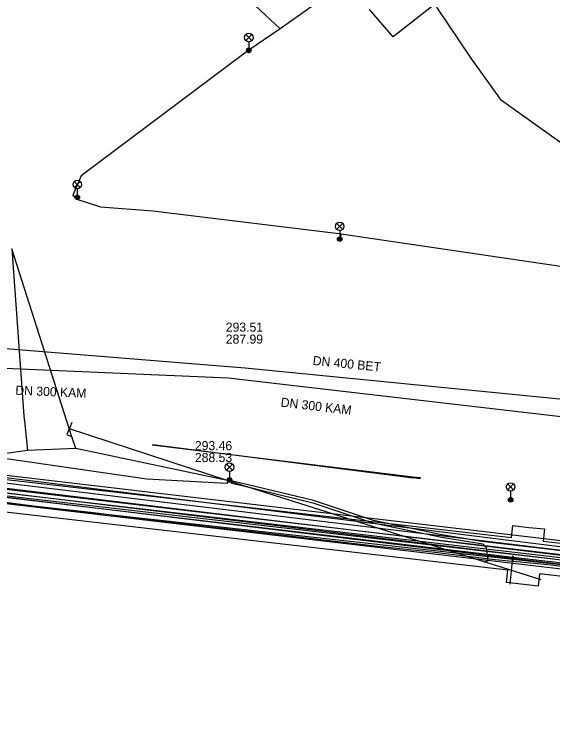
# Model space of a CAD drawing. Extents: x -595540 to -593988, y -1160850 to -1159202.
# Drawn here: x -594463.4 to -594416.1, y -1160027 to -1159965.4 of the extents above; entities that cross this region are included whole.
import ezdxf

# ---------------------------------------------------------------- set-up
doc = ezdxf.new("R2010")
doc.units = 0
for name, color, linetype in [('BKOM-ODVODNENI_trasa sítě', 7, 'Continuous'), ('BVK-DESTOVA_popisy', 7, 'Continuous'), ('BVK-DESTOVA_trasa sítě', 7, 'Continuous'), ('BVK-SPLASKOVA_popisy', 7, 'Continuous'), ('BVK-SPLASKOVA_trasa sítě', 7, 'Continuous'), ('BVK-VODOVOD_trasa sítě', 7, 'Continuous'), ('BVK-VODOVOD_trasa zrušené sítě', 7, 'Continuous'), ('CETIN_kabel podzemní', 7, 'Continuous'), ('DESTOVA_trasa neprovozované sítě', 7, 'Continuous'), ('DPMB_trolejové vedení-nosné lano', 7, 'Continuous'), ('DSP-NN-TEPLARNY_kabel', 7, 'Continuous'), ('EON-VN_kabel', 7, 'Continuous'), ('PODA_kabel optický', 7, 'Continuous'), ('QUANTCOM_kabel v kolektoru_kabelovodu', 7, 'Continuous'), ('TEPLARNY-ELEKTRO_kabel', 7, 'Continuous'), ('TEPLARNY-HORKOVODY_trasa sítě', 7, 'Continuous'), ('TEPLARNY-HORKOVODY_trasa sítě obvodem', 7, 'Continuous'), ('TSB_kabel VO', 7, 'Continuous'), ('TSB_kolektor', 7, 'Continuous'), ('TSB_lampy VO', 7, 'Continuous')]:
    doc.layers.add(name, color=color, linetype=linetype)

msp = doc.modelspace()

# ---------------------------------------------------------------- linework, layer by layer
at = {"layer": 'BKOM-ODVODNENI_trasa sítě'}
for points in [[(-594428.368, -1160006.091), (-594451.23, -1160003.162)], [(-594428.383, -1160006.029), (-594427.719, -1160006.112)]]:
    msp.add_lwpolyline(points, dxfattribs=at)
at = {"layer": 'BVK-DESTOVA_popisy'}
msp.add_line((-594444.809, -1159993.367), (-594444.809, -1159993.367), dxfattribs=at)
at = {"layer": 'BVK-DESTOVA_trasa sítě'}
for p, q in [((-594443.105, -1159996.452), (-594483.447, -1159993.19)), ((-594402.759, -1160000.428), (-594443.105, -1159996.452))]:
    msp.add_line(p, q, dxfattribs=at)
at = {"layer": 'BVK-SPLASKOVA_popisy'}
msp.add_line((-594447.523, -1160002.842), (-594447.523, -1160002.842), dxfattribs=at)
at = {"layer": 'BVK-SPLASKOVA_trasa sítě'}
for p, q in [((-594444.614, -1159997.319), (-594485.93, -1159995.524)), ((-594404.05, -1160002.016), (-594444.614, -1159997.319))]:
    msp.add_line(p, q, dxfattribs=at)
at = {"layer": 'BVK-VODOVOD_trasa sítě'}
for points in [[(-594469.9, -1160007.53), (-594469.248, -1160007.595), (-594468.467, -1160007.674), (-594466.45, -1160007.9), (-594461.46, -1160008.54), (-594456.43, -1160009.12), (-594451.43, -1160009.74), (-594446.44, -1160010.34), (-594441.42, -1160010.9), (-594436.47, -1160011.48), (-594431.46, -1160012.05), (-594426.45, -1160012.6), (-594421.45, -1160013.19), (-594419.668, -1160013.381), (-594419.581, -1160013.39), (-594416.24, -1160013.71), (-594411.23, -1160014.31)], [(-594419.581, -1160013.39), (-594419.55, -1160012.962), (-594419.629, -1160012.953), (-594419.64, -1160013.07), (-594419.86, -1160015.39)]]:
    msp.add_lwpolyline(points, dxfattribs=at)
at = {"layer": 'BVK-VODOVOD_trasa zrušené sítě'}
msp.add_lwpolyline([(-594469.49, -1160007.15), (-594467.97, -1160007.316), (-594419.34, -1160013.06), (-594377.5, -1160017.89), (-594368.46, -1160018.9)], dxfattribs=at)
at = {"layer": 'CETIN_kabel podzemní'}
msp.add_lwpolyline([(-594467.2, -1160005.67), (-594372.02, -1160017.5)], dxfattribs=at)
at = {"layer": 'DESTOVA_trasa neprovozované sítě'}
for p, q in [((-594428.377, -1160006.011), (-594451.265, -1160003.201)), ((-594427.718, -1160006.067), (-594428.377, -1160006.011))]:
    msp.add_line(p, q, dxfattribs=at)
at = {"layer": 'DPMB_trolejové vedení-nosné lano'}
for points in [[(-594458.32, -1160002.47), (-594463.59, -1159985.96)], [(-594463.59, -1159985.96), (-594462.53, -1160000.61)], [(-594462.53, -1160000.61), (-594462.51, -1160000.88)], [(-594462.51, -1160000.88), (-594462.49, -1160001.09)], [(-594462.49, -1160001.09), (-594462.23, -1160003.67)], [(-594458.321, -1160001.211), (-594458.78, -1160002.272)], [(-594458.551, -1160001.742), (-594444.54, -1160006.33)], [(-594458.78, -1160002.272), (-594458.32, -1160002.47)], [(-594457.99, -1160003.5), (-594458.32, -1160002.47)], [(-594457.99, -1160003.5), (-594462.23, -1160003.67)], [(-594444.54, -1160006.33), (-594457.99, -1160003.5)], [(-594462.23, -1160003.67), (-594493.56, -1160008.14)], [(-594444.54, -1160006.33), (-594417.16, -1160015)]]:
    msp.add_lwpolyline(points, dxfattribs=at)
at = {"layer": 'DSP-NN-TEPLARNY_kabel'}
msp.add_lwpolyline([(-594283.249, -1160116.46), (-594281.124, -1160116.689), (-594276.539, -1160074.472), (-594281.251, -1160074.035), (-594280.986, -1160071.341), (-594276.252, -1160071.821), (-594271.794, -1160030.716), (-594278.845, -1160030.006), (-594341.32, -1160022.149), (-594340.664, -1160016.495), (-594343.239, -1160016.186), (-594343.882, -1160021.827), (-594413.657, -1160013.304), (-594469.745, -1160006.777), (-594475.121, -1160046.669), (-594479.045, -1160087.473), (-594484.022, -1160086.945)], dxfattribs=at)
at = {"layer": 'EON-VN_kabel'}
for points in [[(-594325.571, -1160023.302), (-594471.242, -1160005.68), (-594472.063, -1160005.581), (-594472.104, -1160006.031), (-594472.139, -1160006.423), (-594472.175, -1160006.821), (-594472.24, -1160007.542), (-594473.469, -1160021.134), (-594473.505, -1160021.533), (-594474.976, -1160037.793), (-594476.47, -1160052.411), (-594477.178, -1160059.925), (-594477.893, -1160064.161), (-594478.383, -1160071.41), (-594478.563, -1160073.416), (-594479.999, -1160088.093), (-594481.014, -1160094.954), (-594481.712, -1160102.809), (-594481.858, -1160104.428), (-594486.056, -1160148.673), (-594493.705, -1160218.887)], [(-594492.475, -1160219.423), (-594489.792, -1160194.895), (-594488.996, -1160194.982), (-594488.917, -1160194.186), (-594488.878, -1160193.789), (-594484.433, -1160148.844), (-594480.21, -1160104.6), (-594480.065, -1160102.921), (-594479.377, -1160095.153), (-594478.366, -1160088.315), (-594476.911, -1160073.627), (-594476.734, -1160071.423), (-594476.249, -1160064.319), (-594475.559, -1160060.149), (-594474.832, -1160052.566), (-594473.355, -1160037.948), (-594471.909, -1160021.686), (-594471.873, -1160021.287), (-594471.313, -1160014.98), (-594471.277, -1160014.581), (-594470.662, -1160007.663), (-594470.334, -1160007.043), (-594470.133, -1160006.664), (-594325.682, -1160024.094)], [(-594325.626, -1160023.698), (-594470.891, -1160006.17), (-594471.007, -1160006.559), (-594471.123, -1160006.948), (-594471.319, -1160007.604), (-594471.934, -1160014.52), (-594471.97, -1160014.919), (-594472.53, -1160021.226), (-594472.566, -1160021.625), (-594474.012, -1160037.886), (-594475.489, -1160052.502), (-594476.214, -1160060.064), (-594476.905, -1160064.242), (-594477.393, -1160071.374), (-594477.569, -1160073.568), (-594479.021, -1160088.234), (-594480.033, -1160095.076), (-594480.722, -1160102.864), (-594480.867, -1160104.543), (-594485.09, -1160148.781), (-594489.661, -1160193.703), (-594489.269, -1160193.746), (-594488.878, -1160193.789), (-594487.916, -1160193.894)], [(-594325.737, -1160024.49), (-594470.334, -1160007.043), (-594470.704, -1160006.998), (-594471.123, -1160006.948), (-594471.504, -1160006.902), (-594471.871, -1160006.857), (-594472.175, -1160006.821), (-594472.554, -1160006.775), (-594472.634, -1160007.487), (-594473.844, -1160021.095), (-594473.879, -1160021.493), (-594475.326, -1160037.761), (-594476.803, -1160052.372), (-594477.524, -1160059.893), (-594478.218, -1160064.089), (-594478.709, -1160071.276), (-594478.883, -1160073.45), (-594480.331, -1160088.072), (-594481.344, -1160094.921), (-594482.037, -1160102.749), (-594482.182, -1160104.429), (-594486.404, -1160148.653), (-594494.072, -1160218.846)]]:
    msp.add_lwpolyline(points, dxfattribs=at)
at = {"layer": 'PODA_kabel optický'}
msp.add_lwpolyline([(-594271.522, -1160029.628), (-594469.619, -1160007.709), (-594472.621, -1160034.548)], dxfattribs=at)
at = {"layer": 'QUANTCOM_kabel v kolektoru_kabelovodu'}
msp.add_lwpolyline([(-594475.738, -1160059.799), (-594469.854, -1160006.986), (-594376.545, -1160017.729), (-594271.636, -1160029.742)], dxfattribs=at)
at = {"layer": 'TEPLARNY-ELEKTRO_kabel'}
msp.add_lwpolyline([(-594283.249, -1160116.46), (-594281.124, -1160116.689), (-594276.539, -1160074.472), (-594281.251, -1160074.035), (-594280.986, -1160071.341), (-594276.252, -1160071.821), (-594271.794, -1160030.716), (-594278.845, -1160030.006), (-594341.32, -1160022.149), (-594340.664, -1160016.495), (-594343.239, -1160016.186), (-594343.882, -1160021.827), (-594413.657, -1160013.304), (-594469.745, -1160006.777), (-594475.121, -1160046.669), (-594479.045, -1160087.473), (-594484.022, -1160086.945)], dxfattribs=at)
at = {"layer": 'TEPLARNY-HORKOVODY_trasa sítě'}
msp.add_line((-594375.901, -1160017.473), (-594470.487, -1160006.341), dxfattribs=at)
at = {"layer": 'TEPLARNY-HORKOVODY_trasa sítě obvodem'}
for p, q in [((-594471.608, -1160004.95), (-594377.018, -1160016.083)), ((-594376.047, -1160018.714), (-594469.365, -1160007.731))]:
    msp.add_line(p, q, dxfattribs=at)
at = {"layer": 'TSB_kabel VO'}
for points in [[(-594447.5, -1159959.67), (-594440.04, -1159966.66), (-594442.88, -1159968.6), (-594442.76, -1159968.76), (-594442.88, -1159968.6), (-594457.5, -1159979.55), (-594458.25, -1159981.27), (-594457.93, -1159981.52), (-594457.83, -1159981.45), (-594457.93, -1159981.52), (-594457.72, -1159981.68), (-594455.8, -1159982.27), (-594451.22, -1159982.64), (-594434.89, -1159984.61), (-594434.69, -1159984.64), (-594434.8, -1159985.12), (-594434.69, -1159984.64), (-594409.66, -1159988.35)], [(-594437.26, -1159964.7), (-594440.04, -1159966.66), (-594447.5, -1159959.67)], [(-594426.48, -1159964.53), (-594430.12, -1159967.35), (-594432.19, -1159964.96)], [(-594414.48, -1159977.32), (-594420.59, -1159972.96), (-594423.2, -1159969.33), (-594426.29, -1159964.76)], [(-594412.83, -1160012.77), (-594422.33, -1160011.64), (-594425.83, -1160011.08), (-594431.85, -1160009.82), (-594437.11, -1160008.06), (-594443.46, -1160006.52), (-594444.22, -1160006.36), (-594444.48, -1160006.25), (-594444.76, -1160006.57), (-594451.74, -1160006.18), (-594464.26, -1160004.37), (-594464.72, -1160004.31), (-594464.99, -1160004.73), (-594465.49, -1160007.48), (-594465.361, -1160007.77)], [(-594444.48, -1160006.25), (-594444.319, -1160006.542), (-594443.502, -1160006.717), (-594437.168, -1160008.256), (-594431.906, -1160010.017), (-594425.868, -1160011.278), (-594422.232, -1160011.858), (-594421.94, -1160012.18), (-594421.81, -1160013.34), (-594422.16, -1160013.49)]]:
    msp.add_lwpolyline(points, dxfattribs=at)
at = {"layer": 'TSB_kolektor'}
msp.add_lwpolyline([(-594409.935, -1160015.334), (-594417.262, -1160014.491), (-594417.382, -1160015.56), (-594420.165, -1160015.248), (-594420.044, -1160014.171), (-594467.234, -1160008.737), (-594466.91, -1160005.876), (-594419.724, -1160011.308), (-594419.604, -1160010.239), (-594418.21, -1160010.41), (-594416.821, -1160010.551), (-594416.942, -1160011.629), (-594376.379, -1160016.282)], dxfattribs=at)
at = {"layer": 'TSB_lampy VO'}
for p, q in [((-594443.055, -1159967.68), (-594442.525, -1159967.15)), ((-594443.055, -1159967.15), (-594442.525, -1159967.68)), ((-594443.055, -1159967.68), (-594442.525, -1159967.15)), ((-594443.055, -1159967.15), (-594442.525, -1159967.68)), ((-594442.79, -1159967.79), (-594442.79, -1159968.54)), ((-594442.79, -1159967.79), (-594442.79, -1159968.54)), ((-594458.115, -1159980.59), (-594457.585, -1159980.06)), ((-594458.115, -1159980.06), (-594457.585, -1159980.59)), ((-594458.115, -1159980.59), (-594457.585, -1159980.06)), ((-594458.115, -1159980.06), (-594457.585, -1159980.59)), ((-594457.85, -1159980.7), (-594457.85, -1159981.45)), ((-594457.85, -1159980.7), (-594457.85, -1159981.45)), ((-594435.075, -1159984.26), (-594434.545, -1159983.73)), ((-594435.075, -1159983.73), (-594434.545, -1159984.26)), ((-594435.075, -1159984.26), (-594434.545, -1159983.73)), ((-594435.075, -1159983.73), (-594434.545, -1159984.26)), ((-594434.81, -1159984.37), (-594434.81, -1159985.12)), ((-594434.81, -1159984.37), (-594434.81, -1159985.12)), ((-594444.744, -1160005.39), (-594444.214, -1160004.86)), ((-594444.744, -1160004.86), (-594444.214, -1160005.39)), ((-594444.744, -1160005.39), (-594444.214, -1160004.86)), ((-594444.744, -1160004.86), (-594444.214, -1160005.39)), ((-594444.479, -1160005.5), (-594444.479, -1160006.25)), ((-594444.479, -1160005.5), (-594444.479, -1160006.25)), ((-594420.065, -1160007.13), (-594419.535, -1160006.6)), ((-594420.065, -1160006.6), (-594419.535, -1160007.13)), ((-594420.065, -1160007.13), (-594419.535, -1160006.6)), ((-594420.065, -1160006.6), (-594419.535, -1160007.13)), ((-594419.8, -1160007.24), (-594419.8, -1160007.99)), ((-594419.8, -1160007.24), (-594419.8, -1160007.99))]:
    msp.add_line(p, q, dxfattribs=at)
for centre, radius in [((-594442.79, -1159967.415), 0.375), ((-594442.79, -1159967.415), 0.375), ((-594442.79, -1159968.54), 0.2), ((-594442.79, -1159968.54), 0.2), ((-594442.79, -1159968.54), 0.145), ((-594442.79, -1159968.54), 0.145), ((-594442.79, -1159968.54), 0.0876), ((-594442.79, -1159968.54), 0.0876), ((-594457.85, -1159980.325), 0.375), ((-594457.85, -1159980.325), 0.375), ((-594457.85, -1159981.45), 0.2), ((-594457.85, -1159981.45), 0.2), ((-594457.85, -1159981.45), 0.145), ((-594457.85, -1159981.45), 0.145), ((-594457.85, -1159981.45), 0.0876), ((-594457.85, -1159981.45), 0.0876), ((-594434.81, -1159983.995), 0.375), ((-594434.81, -1159983.995), 0.375), ((-594434.81, -1159985.12), 0.2), ((-594434.81, -1159985.12), 0.2), ((-594434.81, -1159985.12), 0.145), ((-594434.81, -1159985.12), 0.145), ((-594434.81, -1159985.12), 0.0876), ((-594434.81, -1159985.12), 0.0876), ((-594444.479, -1160005.125), 0.375), ((-594444.479, -1160005.125), 0.375), ((-594444.479, -1160006.25), 0.2), ((-594444.479, -1160006.25), 0.2), ((-594444.479, -1160006.25), 0.145), ((-594444.479, -1160006.25), 0.145), ((-594444.479, -1160006.25), 0.0876), ((-594444.479, -1160006.25), 0.0876), ((-594419.8, -1160006.865), 0.375), ((-594419.8, -1160006.865), 0.375), ((-594419.8, -1160007.99), 0.2), ((-594419.8, -1160007.99), 0.2), ((-594419.8, -1160007.99), 0.145), ((-594419.8, -1160007.99), 0.145), ((-594419.8, -1160007.99), 0.0876), ((-594419.8, -1160007.99), 0.0876)]:
    msp.add_circle(centre, radius, dxfattribs=at)

# ---------------------------------------------------------------- texts
at = {"layer": 'BVK-DESTOVA_popisy'}
for s, p in [('293.51', (-594444.809, -1159993.242)), ('287.99', (-594444.809, -1159994.292))]:
    msp.add_text(s, height=0.8, dxfattribs=at).set_placement(p)
msp.add_text('DN 400 BET', height=0.8, rotation=354.3744, dxfattribs=at).set_placement((-594437.204, -1159996.151))
at = {"layer": 'BVK-SPLASKOVA_popisy'}
for rotation, p in [(357.52566, (-594463.3, -1159998.77)), (353.40037, (-594440.02, -1159999.811))]:
    msp.add_text('DN 300 KAM', height=0.8, rotation=rotation, dxfattribs=at).set_placement(p)
for s, p in [('293.46', (-594447.523, -1160003.642)), ('288.53', (-594447.523, -1160004.682))]:
    msp.add_text(s, height=0.8, dxfattribs=at).set_placement(p)

doc.saveas('drawing.dxf')
